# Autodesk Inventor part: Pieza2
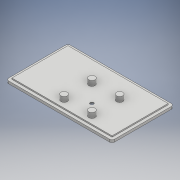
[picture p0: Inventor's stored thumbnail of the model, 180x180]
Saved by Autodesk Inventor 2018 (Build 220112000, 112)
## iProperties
Created: 2020-12
Part Number: Pieza2
Material: Genérico
Document SubType Name: Modeling
Designer: ULISES
Density: 1 g/cm^3
Appearance: Valor por defecto
Author: ULISES
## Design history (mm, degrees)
sketch "Boceto1"
  geometry: L1 (0, 0)-(80, 0); L2 (80, 0)-(80, 45); L3 (80, 45)-(0, 45); L4 (0, 45)-(0, 0); L5 (26, 9.5)-(26, 4.5); L6 (25.4, 9.5)-(25.4, 4.5); L7 (26.6, 4.5)-(26.6, 9.5); L8 (28.5, 8.25)-(28.5, 5.75); L9 (27.9, 8.25)-(27.9, 5.75); L10 (29.1, 5.75)-(29.1, 8.25); L11 (23.5, 8.25)-(23.5, 5.75); L12 (22.9, 5.75)-(22.9, 8.25); L13 (24.1, 8.25)-(24.1, 5.75); C1 r 4.4 at (69, 28); C2 r 4.4 at (69, 6); C3 r 4.4 at (58, 17); C4 r 4.4 at (47, 28); C5 r 4.4 at (47, 6); C6 r 4.4 at (36, 17); C7 r 9 at (12, 17); C8 r 4.4 at (26, 7); C9 r 1.75 at (69, 35.5); A1 r 0.6 centre (26, 9.5) between (26.6, 9.5) and (25.4, 9.5); A2 r 0.6 centre (26, 4.5) between (25.4, 4.5) and (26.6, 4.5); A3 r 0.6 centre (28.5, 8.25) between (29.1, 8.25) and (27.9, 8.25); A4 r 0.6 centre (28.5, 5.75) between (27.9, 5.75) and (29.1, 5.75); A5 r 0.6 centre (23.5, 8.25) between (24.1, 8.25) and (22.9, 8.25); A6 r 0.6 centre (23.5, 5.75) between (22.9, 5.75) and (24.1, 5.75); 3 further points
  constraints: 32 end point, 15 centre point, 12 point on circle, 8 tangent, 7 symmetric about line, 4 horizontal alignment, 4 parallel, 3 vertical alignment, 2 midpoint, 2 vertical, 1 coincident, 1 horizontal, 1 perpendicular, 2 other
  dimensions: "d0" = 7.5 distance of C1.centre C9.centre; "d1" = 22 distance of C2.centre C1.centre (= d2); "d2" = 22 distance of C1.centre C4.centre; "d3" = 11 horizontal distance of C4.centre C3.centre (= 0.5 x d2); "d4" = 11 horizontal distance of C6.centre C4.centre (= d3); "d5" = 11 horizontal distance of C4.centre C3.centre (= d3); "d6" = 24 distance of C6.centre C7.centre; "d7" = 10 horizontal distance of C6.centre C8.centre; "d8" = 10 horizontal distance of C8.centre C6.centre (= d7); "d9" = 17 distance from line of L3 C1.centre; "d10" = 6 distance from line of L1 C2.centre; "d12" = 33 distance from line of L2 C4.centre; "d13" = 12 distance from line of L4 C7.centre; "d14" = 3.5 diameter of C9; "d15" = 8.8 diameter of C1; "d16" = 8.8 diameter of C2; "d17" = 8.8 diameter of C3; "d18" = 8.8 diameter of C5; "d19" = 8.8 diameter of C4; "d20" = 8.8 diameter of C6; "d21" = 8.8 diameter of C8; "d22" = 5 distance of L5.start L5.end; "d23" = 0.6 distance between parallel lines of L7 L5; "d24" = 0.6 distance between parallel lines of L10 L8; "d25" = 2.5 distance between parallel lines of L5 L8; "d26" = 2.5 distance of L8.start L8.end (= 0.5 x d22); "d27" = 1.25 vertical distance of L5.end L8.end (= 0.5 x d26); "d28" = 18 diameter of C7
extrude "Extrusión1" new body sketch "Boceto1" distance "d29" = 2; taper "d30" = 0 deg
sketch "Boceto2"
  geometry: L1 (26.6, 9.5)-(26.6, 4.5) reference; L2 (25.4, 4.5)-(25.4, 9.5) reference; L3 (22.9, 5.75)-(22.9, 8.25) reference; L4 (24.1, 8.25)-(24.1, 5.75) reference; L5 (29.1, 8.25)-(29.1, 5.75) reference; L6 (27.9, 5.75)-(27.9, 8.25) reference; L7 (0, 0)-(80, 0) reference; L8 (80, 0)-(80, 45) reference; L9 (80, 45)-(0, 45) reference; L10 (0, 45)-(0, 0) reference; L11 (82, 47)-(82, -2); L12 (82, -2)-(-2, -2); L13 (-2, -2)-(-2, 47); L14 (-2, 47)-(82, 47); C1 r 9 at (12, 17) reference; C2 r 4.4 at (36, 17) reference; C3 r 4.4 at (47, 6) reference; C4 r 4.4 at (47, 28) reference; C5 r 4.4 at (58, 17) reference; C6 r 4.4 at (69, 6) reference; C7 r 4.4 at (69, 28) reference; C8 r 1.75 at (69, 35.5) reference; A1 r 0.6 centre (26, 9.5) between (26.6, 9.5) and (25.4, 9.5) reference; A2 r 0.6 centre (26, 4.5) between (25.4, 4.5) and (26.6, 4.5) reference; A3 r 0.6 centre (23.5, 5.75) between (22.9, 5.75) and (24.1, 5.75) reference; A4 r 0.6 centre (23.5, 8.25) between (24.1, 8.25) and (22.9, 8.25) reference; A5 r 0.6 centre (28.5, 8.25) between (29.1, 8.25) and (27.9, 8.25) reference; A6 r 0.6 centre (28.5, 5.75) between (27.9, 5.75) and (29.1, 5.75) reference; 1 further point
  constraints: 8 end point, 3 other
  dimensions: "d31" = 2 distance between parallel lines of L8 L11
extrude "Extrusión2" join sketch "Boceto2" distance "d32" = 22; taper "d33" = 0 deg
fillet "Empalme2" dims "d35" = 2
sketch "Boceto3"
  geometry: C1 r 4.4 at (-47, 28) reference; C2 r 4.4 at (-58, 17) reference; C3 r 4.4 at (-36, 17) reference; C4 r 4.4 at (-47, 6) reference; C5 r 3.5 at (-49.5, 14.5); C6 r 1.4 at (-49.5, 14.5); 1 further point
  constraints: 2 centre point, 1 coincident
  dimensions: "d36" = 2.5 horizontal distance of C4.centre C5.centre; "d37" = 2.5 vertical distance of C2.centre C5.centre; "d38" = 2.8 diameter of C6; "d39" = 7 diameter of C5
extrude "Extrusión3" join sketch "Boceto3" distance "d40" = 10; taper "d41" = 0 deg
fillet "Empalme3" dims "d42" = 2
sketch "Boceto5"
  geometry: L1 (0, 0)-(-80, 0) reference; L2 (0, 45)-(0, 0) reference; L3 (-80, 45)-(0, 45) reference; L4 (-80, 0)-(-80, 45) reference; L5 (-27.9, 8.25)-(-27.9, 5.75) reference; L6 (-29.1, 5.75)-(-29.1, 8.25) reference; L7 (-24.1, 5.75)-(-24.1, 8.25) reference; L8 (-22.9, 8.25)-(-22.9, 5.75) reference; L9 (-25.4, 9.5)-(-25.4, 4.5) reference; L10 (-26.6, 4.5)-(-26.6, 9.5) reference; L11 (-5, 45)-(0, 40); L12 (0, 45)-(-80, 45) reference; L13 (-5, 45)-(0, 45); L14 (0, 45)-(0, 40); L15 (0, 0)-(0, 45) reference; L16 (0, 22.5)-(-3.469, 22.5); L17 (-5, 0)-(0, 0); L18 (0, 0)-(0, 5); L19 (-5, 0)-(0, 5); L20 (-40, 45)-(-40, 40); L21 (-80, 0)-(-80, 5); L22 (-75, 0)-(-80, 0); L23 (-75, 0)-(-80, 5); L24 (-80, 45)-(-80, 0); L25 (-80, 0)-(-80, 45); L26 (-80, 0)-(0, 0); L27 (-80, 45)-(0, 45); L28 (0, 45)-(-80, 45); L29 (-75, 45)-(-80, 40); L30 (-80, 45)-(-80, 40); L31 (-75, 45)-(-80, 45); L32 (-80, 22.5)-(-76.531, 22.5); C1 r 1.75 at (-69, 35.5) reference; C2 r 4.4 at (-69, 28) reference; C3 r 4.4 at (-69, 6) reference; C4 r 4.4 at (-47, 28) reference; C5 r 4.4 at (-36, 17) reference; C6 r 9 at (-12, 17) reference; C7 r 9 at (-68, 17); A1 r 5.5 centre (-49.5, 14.5) between (-45.974, 10.279) and (-53.721, 18.026) reference; A2 r 4.4 centre (-47, 6) between (-50.179, 9.042) and (-45.974, 10.279) reference; A3 r 5.5 centre (-49.5, 14.5) between (-54.958, 13.821) and (-50.179, 9.042) reference; A4 r 4.4 centre (-58, 17) between (-53.721, 18.026) and (-54.958, 13.821) reference; A5 r 0.6 centre (-28.5, 8.25) between (-27.9, 8.25) and (-29.1, 8.25) reference; A6 r 0.6 centre (-28.5, 5.75) between (-29.1, 5.75) and (-27.9, 5.75) reference; A7 r 0.6 centre (-23.5, 5.75) between (-24.1, 5.75) and (-22.9, 5.75) reference; A8 r 0.6 centre (-23.5, 8.25) between (-22.9, 8.25) and (-24.1, 8.25) reference; A9 r 0.6 centre (-26, 9.5) between (-25.4, 9.5) and (-26.6, 9.5) reference; A10 r 0.6 centre (-26, 4.5) between (-26.6, 4.5) and (-25.4, 4.5) reference
  constraints: 40 end point, 14 symmetric about line, 4 point on line, 2 midpoint, 1 centre point, 1 collinear, 1 horizontal, 1 perpendicular, 1 vertical, 1 other
  dimensions: "d43" = 5 distance of L2.start L11.end; "d44" = 5 distance of L2.start L11.start
extrude "Extrusión4" join sketch "Boceto5" distance "d45" = 10; taper "d46" = 0 deg
sketch "Boceto6"
  geometry: L1 (-80, 0)-(-80, 45) reference; L2 (-80, 45)-(0, 45) reference; L3 (0, 45)-(0, 0) reference; L4 (0, 0)-(-80, 0) reference; L5 (-80, -2)-(0, -2) reference; L6 (2, 0)-(2, 45) reference; L7 (0, 47)-(-80, 47) reference; L8 (-82, 45)-(-82, 0) reference; L9 (-0.3, 0.3)-(-0.3, 44.7); L10 (-0.3, 44.7)-(-79.7, 44.7); L11 (-79.7, 44.7)-(-79.7, 0.3); L12 (-79.7, 0.3)-(-0.3, 0.3); L13 (-25.4, 9.5)-(-25.4, 4.5) reference; L14 (-26.6, 4.5)-(-26.6, 9.5) reference; L15 (-24.1, 5.75)-(-24.1, 8.25) reference; L16 (-22.9, 8.25)-(-22.9, 5.75) reference; L17 (-27.9, 8.25)-(-27.9, 5.75) reference; L18 (-29.1, 5.75)-(-29.1, 8.25) reference; L19 (-80, 5)-(-75, 0) reference; L20 (-5, 0)-(-75, 0) reference; L21 (-5, 0)-(0, 5) reference; L22 (0, 40)-(0, 5) reference; L23 (0, 40)-(-5, 45) reference; L24 (-75, 45)-(-5, 45) reference; L25 (-75, 45)-(-80, 40) reference; L26 (-80, 5)-(-80, 40) reference; C1 r 1.4 at (-49.5, 14.5) reference; C2 r 2.5 at (-36, 28); C3 r 2.5 at (-36, 6); C4 r 2.5 at (-58, 28); C5 r 2.5 at (-58, 6); C6 r 9 at (-12, 17) reference; C7 r 4.4 at (-36, 17) reference; C8 r 4.4 at (-47, 28) reference; C9 r 4.4 at (-69, 6) reference; C10 r 4.4 at (-69, 28) reference; C11 r 1.75 at (-69, 35.5) reference; A1 r 2 centre (-80, 0) between (-82, 0) and (-80, -2) reference; A2 r 2 centre (0, 0) between (0, -2) and (2, 0) reference; A3 r 2 centre (0, 45) between (2, 45) and (0, 47) reference; A4 r 2 centre (-80, 45) between (-80, 47) and (-82, 45) reference; A5 r 0.6 centre (-26, 9.5) between (-25.4, 9.5) and (-26.6, 9.5) reference; A6 r 0.6 centre (-26, 4.5) between (-26.6, 4.5) and (-25.4, 4.5) reference; A7 r 0.6 centre (-23.5, 5.75) between (-24.1, 5.75) and (-22.9, 5.75) reference; A8 r 0.6 centre (-23.5, 8.25) between (-22.9, 8.25) and (-24.1, 8.25) reference; A9 r 0.6 centre (-28.5, 8.25) between (-27.9, 8.25) and (-29.1, 8.25) reference; A10 r 0.6 centre (-28.5, 5.75) between (-29.1, 5.75) and (-27.9, 5.75) reference; A11 r 5.5 centre (-49.5, 14.5) between (-45.974, 10.279) and (-53.721, 18.026) reference; A12 r 4.4 centre (-47, 6) between (-50.179, 9.042) and (-45.974, 10.279) reference; A13 r 5.5 centre (-49.5, 14.5) between (-54.958, 13.821) and (-50.179, 9.042) reference; A14 r 4.4 centre (-58, 17) between (-53.721, 18.026) and (-54.958, 13.821) reference; 1 further point
  constraints: 8 end point, 4 centre point, 4 horizontal alignment, 3 other
  dimensions: "d47" = 0.3 distance between parallel lines of L3 L9; "d48" = 11 distance of A12.centre C5.centre; "d49" = 11 distance of C3.centre A12.centre; "d50" = 11 distance of C2.centre C8.centre; "d51" = 11 distance of C8.centre C4.centre; "d52" = 5 diameter of C2; "d53" = 5 diameter of C3; "d54" = 5 diameter of C5; "d55" = 5 diameter of C4
extrude "Extrusión5" join sketch "Boceto6" distance "d56" = 2; taper "d57" = 0 deg
sketch "Boceto8"
  geometry: L1 (-80, 0)-(-80, 45) reference; L2 (-80, 45)-(0, 45) reference; L3 (0, 45)-(0, 0) reference; L4 (0, 0)-(-80, 0) reference; L5 (-80, -2)-(0, -2) reference; L6 (2, 0)-(2, 45) reference; L7 (0, 47)-(-80, 47) reference; L8 (-82, 45)-(-82, 0) reference; L9 (-0.3, 0.3)-(-0.3, 44.7) reference; L10 (-0.3, 44.7)-(-79.7, 44.7) reference; L11 (-79.7, 44.7)-(-79.7, 0.3) reference; L12 (-79.7, 0.3)-(-0.3, 0.3) reference; C1 r 2.5 at (-58, 6) reference; C2 r 2.5 at (-58, 28) reference; C3 r 2.5 at (-36, 6) reference; C4 r 2.5 at (-36, 28) reference; C5 r 1.4 at (-49.5, 14.5) reference; A1 r 2 centre (-80, 0) between (-82, 0) and (-80, -2) reference; A2 r 2 centre (0, 0) between (0, -2) and (2, 0) reference; A3 r 2 centre (0, 45) between (2, 45) and (0, 47) reference; A4 r 2 centre (-80, 45) between (-80, 47) and (-82, 45) reference; 1 further point
extrude "Extrusión6" join sketch "Boceto8" stored distance "d58" = 2; taper "d59" = 0 deg
sketch "Boceto9"
  geometry: L1 (0.3, 0.3)-(0.3, 44.7) reference; L2 (79.7, 0.3)-(0.3, 0.3) reference; L3 (79.7, 44.7)-(79.7, 0.3) reference; L4 (0.3, 44.7)-(79.7, 44.7) reference; L5 (0, 45)-(-2, 45) reference; L6 (-2, 45)-(-2, 0) reference; L7 (-2, 0)-(0, 0) reference; L8 (0, 0)-(0, 45) reference; L9 (80, 0)-(82, 0) reference; L10 (82, 0)-(82, 45) reference; L11 (82, 45)-(80, 45) reference; L12 (80, 45)-(80, 0) reference; L13 (-2, 47)-(82, 47); L14 (82, 47)-(82, -2); L15 (82, -2)-(-2, -2); L16 (-2, -2)-(-2, 47); L17 (82, 0)-(82, 45) reference; L18 (80, 47)-(0, 47) reference; L19 (-2, 45)-(-2, 0) reference; L20 (0, -2)-(80, -2) reference; C1 r 2.5 at (58, 6) reference; C2 r 2.5 at (58, 28) reference; C3 r 2.5 at (36, 6) reference; C4 r 2.5 at (36, 28) reference; C5 r 1.4 at (49.5, 14.5) reference; 1 further point
  constraints: 8 end point, 4 collinear, 2 parallel, 1 horizontal, 1 perpendicular
extrude "Extrusión7" cut sketch "Boceto9" distance "d60" = 50; taper "d61" = 0 deg
sketch "Boceto10"
  geometry: L1 (-80, -2)-(0, -2) reference; L2 (2, 0)-(2, 45) reference; L3 (0, 47)-(-80, 47) reference; L4 (-82, 45)-(-82, 0) reference; C1 r 2.5 at (-36, 28) reference; C2 r 2.5 at (-36, 6) reference; C3 r 2.5 at (-58, 28) reference; C4 r 2.5 at (-58, 6) reference; C5 r 1.4 at (-49.5, 14.5) reference; A1 r 2 centre (-80, 0) between (-82, 0) and (-80, -2) reference; A2 r 2 centre (0, 0) between (0, -2) and (2, 0) reference; A3 r 2 centre (0, 45) between (2, 45) and (0, 47) reference; A4 r 2 centre (-80, 45) between (-80, 47) and (-82, 45) reference; 1 further point
extrude "Extrusión8" join sketch "Boceto10" distance "d62" = 7; taper "d63" = 0 deg
chamfer "Chaflán1" distance "d64" = 3; stored, may be unused: second distance "d65" = 2, angle "d66" = 45 deg
node "Sólido1"
node "Contorno proyectado1"
node "Contorno proyectado8"
node "Contorno proyectado9"
node "Contorno proyectado10"
node "Contorno proyectado11"
node "Contorno proyectado12"
node "Contorno proyectado13"
node "Contorno proyectado14"
node "Contorno proyectado15"
node "Contorno proyectado16"
